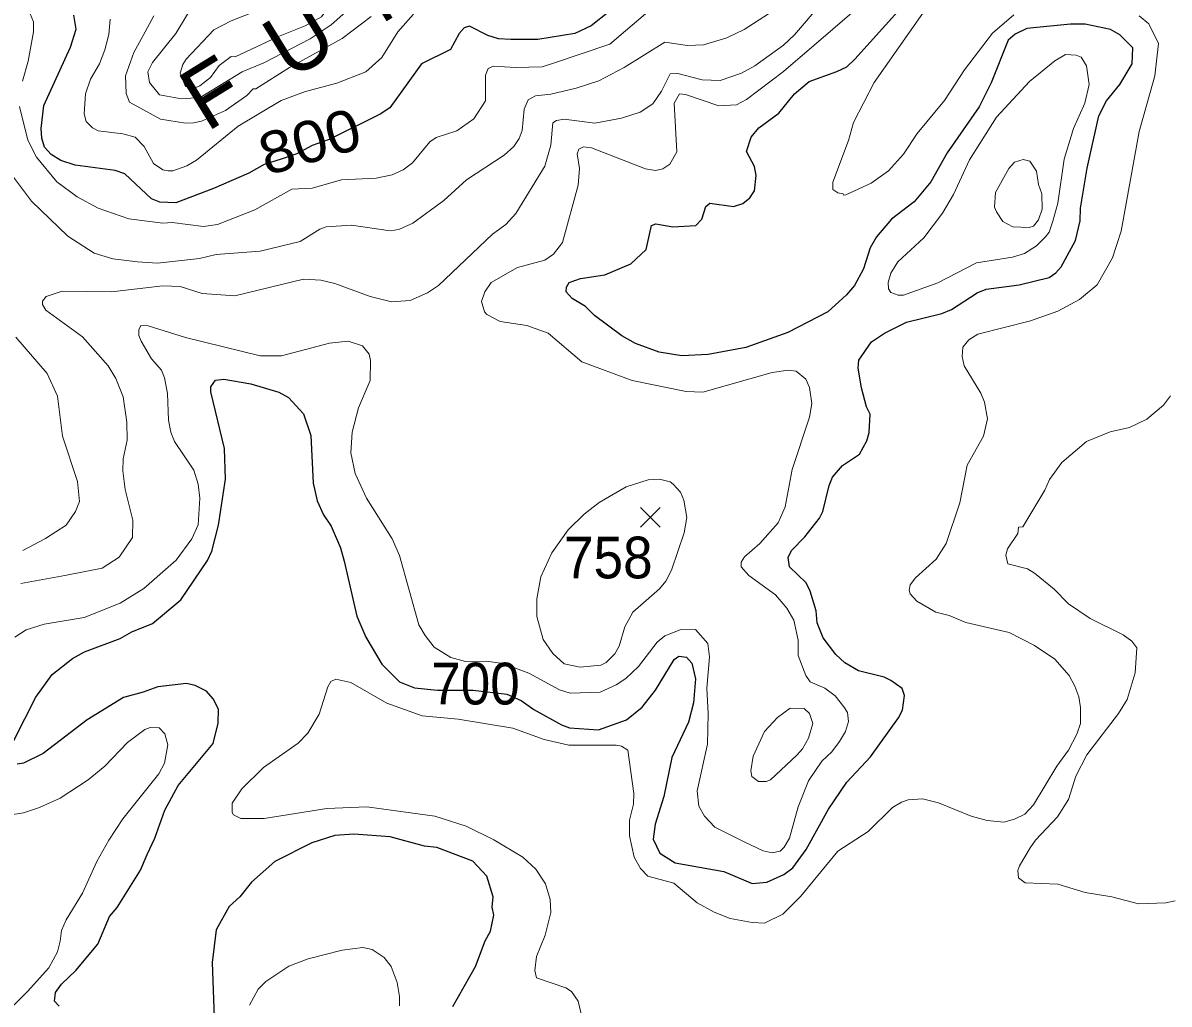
# Model space of a CAD drawing. Extents: x 294.2 to 320.3, y 7482.7 to 7510.7.
# Drawn here: x 308.568 to 310.764, y 7485.877 to 7487.757 of the extents above; entities that cross this region are included whole.
import ezdxf
from ezdxf.enums import TextEntityAlignment as Align

# ---------------------------------------------------------------- set-up
doc = ezdxf.new("R2010")
doc.units = 0
doc.header["$LTSCALE"] = 0.032
for name, color, linetype, lineweight in [('1', 7, 'Continuous', 25), ('2', 7, 'Continuous', 13), ('21', 7, 'Continuous', 25)]:
    doc.layers.add(name, color=color, linetype=linetype, lineweight=lineweight)
doc.layers.add('61', color=7, linetype='Continuous')

msp = doc.modelspace()

# ---------------------------------------------------------------- linework, layer by layer
at = {"layer": '1'}
for points in [[(309.6095, 7487.2508), (309.6145, 7487.26), (309.6361, 7487.2675), (309.6827, 7487.2745), (309.7327, 7487.2954), (309.7618, 7487.3232), (309.7724, 7487.369), (309.7801, 7487.3722), (309.8127, 7487.3666), (309.8571, 7487.3692), (309.8688, 7487.381), (309.8765, 7487.4058), (309.8837, 7487.4117), (309.9292, 7487.4053), (309.9469, 7487.4115), (309.9602, 7487.4222), (309.9697, 7487.4357), (309.9724, 7487.4652), (309.9696, 7487.4824), (309.9541, 7487.5109), (309.963, 7487.5383), (309.978, 7487.5566), (310.0162, 7487.5841), (310.0462, 7487.6213), (310.0742, 7487.6453), (310.1269, 7487.6641), (310.1463, 7487.6733), (310.1618, 7487.6878), (310.2794, 7487.819)], [(308.763, 7487.4681), (308.7447, 7487.4746), (308.6679, 7487.4848), (308.6401, 7487.4934), (308.6221, 7487.5052), (308.6088, 7487.5192), (308.6038, 7487.5364), (308.6027, 7487.5547), (308.608, 7487.5993), (308.6588, 7487.7106), (308.6699, 7487.7456), (308.6654, 7487.7725)], [(309.6902, 7487.7785), (309.6567, 7487.7517), (309.6251, 7487.7371), (309.5544, 7487.7253), (309.5028, 7487.7253), (309.4787, 7487.7269), (309.4582, 7487.7333), (309.4232, 7487.7511), (309.4133, 7487.7479), (309.4038, 7487.7371), (309.3867, 7487.7065), (309.3317, 7487.679), (309.271, 7487.5946), (309.2522, 7487.5822), (309.1545, 7487.5342), (309.1218, 7487.5223), (309.0927, 7487.5062), (309.0627, 7487.4965), (309.03, 7487.4857)], [(309.8491, 7486.5302), (309.8561, 7486.5002), (309.8523, 7486.4543), (309.8427, 7486.4172), (309.8108, 7486.3491), (309.7959, 7486.2743), (309.7793, 7486.2216), (309.7754, 7486.1931), (309.7882, 7486.1662), (309.8176, 7486.1474), (309.9109, 7486.1307), (309.9648, 7486.1076), (309.9931, 7486.1103), (310.0259, 7486.1254), (310.0426, 7486.1377), (310.0687, 7486.1733), (310.1109, 7486.2503), (310.1465, 7486.302), (310.1914, 7486.3504), (310.2452, 7486.4251), (310.253, 7486.4401), (310.2568, 7486.4681), (310.2524, 7486.4815), (310.2308, 7486.4971), (310.218, 7486.5036), (310.1687, 7486.5153), (310.1427, 7486.5307), (310.125, 7486.5468), (310.1012, 7486.5786), (310.0895, 7486.6076), (310.0878, 7486.6302), (310.0762, 7486.6684), (310.0684, 7486.684), (310.0368, 7486.7147), (310.034, 7486.733), (310.0401, 7486.7464), (310.0656, 7486.7722), (310.0939, 7486.8082), (310.1005, 7486.8211), (310.1122, 7486.8706), (310.1188, 7486.8867), (310.1383, 7486.9093), (310.1705, 7486.9309), (310.1845, 7486.9566), (310.189, 7486.9722), (310.1912, 7487.0072), (310.184, 7487.0212), (310.1745, 7487.0577), (310.1679, 7487.0959), (310.1695, 7487.1109), (310.1934, 7487.1464), (310.2183, 7487.163), (310.2605, 7487.184), (310.3282, 7487.2002), (310.3471, 7487.2083), (310.3963, 7487.2402), (310.4133, 7487.2468), (310.4766, 7487.2554), (310.5338, 7487.2691), (310.5466, 7487.2783), (310.5571, 7487.2901), (310.5843, 7487.3402), (310.5932, 7487.3778), (310.5943, 7487.402), (310.6065, 7487.4789), (310.6293, 7487.5794), (310.6437, 7487.6079), (310.6692, 7487.6396), (310.6931, 7487.6789), (310.6942, 7487.7095), (310.6692, 7487.7348), (310.6515, 7487.745), (310.6027, 7487.7547), (310.5749, 7487.7552), (310.4909, 7487.7466), (310.4687, 7487.7359), (310.4554, 7487.7246), (310.4226, 7487.6423), (310.3999, 7487.5965), (310.3386, 7487.5084), (310.3075, 7487.453), (310.2756, 7487.4146), (310.2318, 7487.3813), (310.203, 7487.3474), (310.1908, 7487.3264), (310.178, 7487.2861), (310.1608, 7487.2543), (310.1459, 7487.2361), (310.1098, 7487.2038), (310.0333, 7487.164), (309.9529, 7487.1354), (309.8808, 7487.1221), (309.8304, 7487.1194), (309.787, 7487.1264), (309.7415, 7487.1431)], [(309.03, 7487.4857), (309.0009, 7487.4696), (308.9327, 7487.44), (308.8608, 7487.4127), (308.8303, 7487.4138), (308.8143, 7487.4202), (308.763, 7487.4681)], [(309.7415, 7487.1431), (309.7154, 7487.1577), (309.6627, 7487.1965), (309.6455, 7487.2137), (309.6198, 7487.229), (309.6089, 7487.2417), (309.6095, 7487.2508)], [(308.5502, 7486.3819), (308.5924, 7486.4652), (308.6235, 7486.5082), (308.6628, 7486.5389), (308.6856, 7486.5518), (308.7538, 7486.5775), (308.7766, 7486.5904), (308.8157, 7486.6064), (308.8701, 7486.6516), (308.9217, 7486.7268), (308.93, 7486.7446), (308.9422, 7486.7946), (308.9561, 7486.8829), (308.9541, 7486.9416), (308.9275, 7487.0503), (308.9281, 7487.06), (308.9369, 7487.0724), (308.953, 7487.0745), (309.0046, 7487.0659), (309.0579, 7487.0498), (309.0767, 7487.0396), (309.1056, 7487.0078), (309.1195, 7486.9664), (309.1236, 7486.8749), (309.1314, 7486.8416), (309.1436, 7486.8147), (309.1586, 7486.7926), (309.1763, 7486.7512), (309.183, 7486.7254), (309.2074, 7486.6205), (309.2246, 7486.5802), (309.2557, 7486.528), (309.2895, 7486.4941), (309.3179, 7486.4829), (309.3618, 7486.4786), (309.4301, 7486.4786), (309.4951, 7486.471), (309.5222, 7486.4587), (309.5465, 7486.4414), (309.5995, 7486.4121), (309.6148, 7486.4063), (309.6703, 7486.4025), (309.724, 7486.4216)], [(309.724, 7486.4216), (309.754, 7486.4459), (309.7795, 7486.4785), (309.8153, 7486.5372), (309.8242, 7486.5436), (309.8389, 7486.5417), (309.8491, 7486.5302)], [(308.6375, 7485.8724), (308.6281, 7485.8821), (308.6303, 7485.8988), (308.6414, 7485.9149), (308.6691, 7485.9408), (308.7113, 7485.9913), (308.7339, 7486.0448), (308.7484, 7486.062), (308.7933, 7486.1335), (308.8061, 7486.1636), (308.8205, 7486.1948), (308.8394, 7486.2485), (308.8654, 7486.2959), (308.9325, 7486.3765), (308.9419, 7486.4152), (308.9425, 7486.4421), (308.9325, 7486.462), (308.9197, 7486.4765), (308.8975, 7486.4872), (308.8809, 7486.491), (308.826, 7486.4851), (308.7983, 7486.4743), (308.7605, 7486.4646), (308.6906, 7486.4216), (308.6068, 7486.357), (308.5691, 7486.3388), (308.5569, 7486.3366)], [(309.3915, 7485.8722), (309.4351, 7485.9486), (309.4535, 7485.9981), (309.4635, 7486.0164), (309.4701, 7486.047), (309.4668, 7486.0626), (309.4685, 7486.0825), (309.4568, 7486.1218), (309.4297, 7486.1509), (309.3607, 7486.1768), (309.3369, 7486.1795), (309.2714, 7486.1972), (309.202, 7486.2025), (309.1654, 7486.1999), (309.1215, 7486.1859), (309.0504, 7486.1503), (309.0054, 7486.1105), (308.9832, 7486.0825)], [(308.9832, 7486.0825), (308.9632, 7486.0636), (308.9382, 7486.019), (308.9305, 7485.9565), (308.9358, 7485.7983), (308.9497, 7485.7295), (308.9699, 7485.6695)]]:
    msp.add_lwpolyline(points, dxfattribs=at)
at = {"layer": '2'}
for points in [[(308.53, 7487.8576), (308.5722, 7487.7976), (308.5881, 7487.7593), (308.5881, 7487.7401), (308.5779, 7487.684), (308.5671, 7487.6456)], [(309.837, 7487.6201), (309.9009, 7487.5984), (309.9347, 7487.6003), (309.9538, 7487.6105), (310.0247, 7487.6641), (310.2143, 7487.8269), (310.2399, 7487.8691)], [(309.2317, 7487.8193), (309.1583, 7487.7535), (309.1182, 7487.7269), (309.0295, 7487.6811), (308.9878, 7487.6635), (308.9074, 7487.6144), (308.8716, 7487.6118), (308.8295, 7487.6195), (308.8103, 7487.6431), (308.8071, 7487.6635), (308.8161, 7487.6814), (308.8608, 7487.7369), (308.8978, 7487.7982)], [(308.5249, 7487.495), (308.5843, 7487.4158), (308.6539, 7487.3487), (308.7043, 7487.3161), (308.7401, 7487.3053), (308.7873, 7487.2995), (308.8257, 7487.297), (308.9061, 7487.3059), (308.938, 7487.3136), (309.0223, 7487.32), (309.0989, 7487.3385), (309.1366, 7487.3621), (309.1487, 7487.3666), (309.1972, 7487.3698), (309.2713, 7487.359), (309.2879, 7487.3615), (309.3147, 7487.3736), (309.3741, 7487.417), (309.4175, 7487.4566), (309.4897, 7487.5039), (309.5082, 7487.5205), (309.5184, 7487.5358), (309.5241, 7487.5512), (309.5279, 7487.592), (309.5356, 7487.6099), (309.5497, 7487.6175), (309.5791, 7487.6207), (309.6276, 7487.6322), (309.671, 7487.6463), (309.7195, 7487.6718), (309.7974, 7487.7203), (309.8408, 7487.714), (309.8717, 7487.7152), (309.9162, 7487.7286), (309.9494, 7487.7446), (310.0426, 7487.8052)], [(308.5613, 7487.5971), (308.5773, 7487.5326), (308.5939, 7487.5001), (308.6328, 7487.4528), (308.6717, 7487.4241), (308.712, 7487.4024), (308.7707, 7487.382), (308.8359, 7487.3736), (308.8537, 7487.3749), (308.9138, 7487.3672), (308.9406, 7487.3711), (309.0121, 7487.3992), (309.0829, 7487.4387), (309.1219, 7487.4407), (309.1781, 7487.4566), (309.2445, 7487.4598), (309.2751, 7487.4662), (309.2962, 7487.4758), (309.3141, 7487.4892), (309.3473, 7487.5294), (309.3594, 7487.5377), (309.399, 7487.5505), (309.4315, 7487.5735), (309.4539, 7487.608), (309.4539, 7487.6571), (309.459, 7487.6699), (309.4692, 7487.6744), (309.5114, 7487.6718), (309.5625, 7487.6731), (309.5842, 7487.6801), (309.6921, 7487.7169), (309.7776, 7487.7893)], [(310.0988, 7487.7963), (310.0458, 7487.7344), (310.0247, 7487.7146)], [(310.3133, 7487.8065), (310.199, 7487.6431), (310.1594, 7487.5665), (310.1498, 7487.532), (310.1192, 7487.4522), (310.1198, 7487.4381), (310.1294, 7487.4317), (310.1396, 7487.4298), (310.1402, 7487.4273), (310.1447, 7487.4279), (310.1932, 7487.4502), (310.2264, 7487.4739), (310.2552, 7487.5058), (310.2813, 7487.5454), (310.3337, 7487.6086), (310.372, 7487.6674), (310.4256, 7487.7376), (310.4665, 7487.7727)], [(309.3162, 7487.7739), (309.2862, 7487.7406), (309.2553, 7487.6909), (309.2247, 7487.6635), (309.1692, 7487.6418), (309.1091, 7487.6258), (309.0625, 7487.6086), (308.9801, 7487.5594), (308.9003, 7487.4943), (308.8818, 7487.4834), (308.855, 7487.4739), (308.8461, 7487.4739), (308.8359, 7487.4758), (308.8179, 7487.4879), (308.8001, 7487.5205), (308.7828, 7487.5384), (308.7593, 7487.5447), (308.712, 7487.5505), (308.7011, 7487.5563), (308.689, 7487.5684), (308.6851, 7487.5831), (308.6877, 7487.6214), (308.6973, 7487.6495), (308.7145, 7487.6789), (308.7247, 7487.7057), (308.7324, 7487.735), (308.7349, 7487.7644)], [(309.2347, 7487.7696), (309.1793, 7487.7276), (309.0782, 7487.6722), (309.014, 7487.6309), (309.0089, 7487.6309), (308.9967, 7487.6181), (308.9559, 7487.5894), (308.9099, 7487.569), (308.8946, 7487.5658), (308.8793, 7487.5652), (308.8314, 7487.5728), (308.772, 7487.6052), (308.7653, 7487.6224), (308.7643, 7487.6559), (308.7803, 7487.7006), (308.7982, 7487.7331), (308.8186, 7487.7708)], [(310.7066, 7487.7708), (310.7251, 7487.7554), (310.7436, 7487.7178), (310.7366, 7487.6559), (310.7277, 7487.6239), (310.7066, 7487.5492), (310.6721, 7487.3583), (310.6555, 7487.3073), (310.6261, 7487.2555), (310.5923, 7487.2274), (310.5508, 7487.2051), (310.4985, 7487.1866), (310.3976, 7487.161), (310.3803, 7487.1502)], [(310.0247, 7487.7146), (309.9698, 7487.675), (309.9443, 7487.6609), (309.9034, 7487.6469), (309.8689, 7487.6482), (309.8223, 7487.6603), (309.8076, 7487.6596)], [(309.8076, 7487.6596), (309.791, 7487.6265), (309.7744, 7487.6022), (309.7502, 7487.5863), (309.7144, 7487.5748), (309.6633, 7487.5652), (309.6046, 7487.5728), (309.5899, 7487.5703), (309.5829, 7487.5658), (309.579, 7487.5231), (309.5676, 7487.4826), (309.512, 7487.3921), (309.4928, 7487.3711), (309.4673, 7487.3526), (309.3639, 7487.2542), (309.3428, 7487.2402), (309.3096, 7487.2255), (309.2739, 7487.2229), (309.233, 7487.2331), (309.1653, 7487.2581), (309.1385, 7487.2645), (309.1053, 7487.2663), (308.9738, 7487.2344), (308.9112, 7487.2389), (308.8691, 7487.2523), (308.8359, 7487.2536), (308.7375, 7487.2421), (308.6431, 7487.2434), (308.6124, 7487.2332), (308.6054, 7487.2243), (308.6054, 7487.2179), (308.6118, 7487.207), (308.682, 7487.1559), (308.7311, 7487.1004), (308.7458, 7487.0761), (308.7599, 7487.0404), (308.7669, 7486.9918), (308.7675, 7486.9574), (308.7599, 7486.9216), (308.7592, 7486.8986), (308.7637, 7486.8629), (308.7784, 7486.8041), (308.7778, 7486.7709), (308.7522, 7486.7333), (308.7197, 7486.7122), (308.6482, 7486.6981), (308.5639, 7486.6828)], [(309.3383, 7486.5832), (309.3556, 7486.5609), (309.3875, 7486.541), (309.4156, 7486.5334), (309.4552, 7486.534), (309.4877, 7486.5295), (309.5369, 7486.5111), (309.5957, 7486.4791), (309.6161, 7486.4728), (309.6736, 7486.4746), (309.7042, 7486.4887), (309.7227, 7486.5009), (309.747, 7486.5238), (309.7827, 7486.5704), (309.7974, 7486.5826), (309.8268, 7486.5941), (309.8561, 7486.5947), (309.8798, 7486.5679), (309.8829, 7486.5424), (309.8778, 7486.4823), (309.8804, 7486.4338), (309.8791, 7486.3751), (309.8599, 7486.2857), (309.8625, 7486.2563), (309.8734, 7486.2372), (309.8932, 7486.2155), (309.9494, 7486.188), (309.9858, 7486.1707), (310.003, 7486.1669), (310.0183, 7486.1701), (310.026, 7486.1772), (310.0362, 7486.195), (310.0528, 7486.255), (310.0732, 7486.3048), (310.0987, 7486.3425), (310.1179, 7486.3604), (310.1326, 7486.3802), (310.1441, 7486.3993), (310.1498, 7486.4185), (310.1478, 7486.4355), (310.1409, 7486.4466), (310.1243, 7486.4677), (310.1039, 7486.4823), (310.0764, 7486.4945), (310.0681, 7486.5066), (310.0528, 7486.5449), (310.0528, 7486.5743), (310.0445, 7486.6126), (310.0311, 7486.6356), (310.0094, 7486.6611), (309.9583, 7486.6981), (309.9442, 7486.7147), (309.9442, 7486.7236), (309.95, 7486.7339), (309.9794, 7486.7594), (310.0145, 7486.799), (310.0279, 7486.8297), (310.0419, 7486.9012), (310.0745, 7487.002), (310.0796, 7487.0276), (310.0745, 7487.0583), (310.0675, 7487.0748), (310.049, 7487.0901), (310.0337, 7487.0921), (310.003, 7487.087), (309.8702, 7487.0499), (309.8383, 7487.0512), (309.7348, 7487.0717), (309.6384, 7487.108), (309.5739, 7487.1629), (309.5331, 7487.1776), (309.482, 7487.1853), (309.4564, 7487.1987), (309.452, 7487.2038), (309.4461, 7487.2233), (309.4526, 7487.2421), (309.4647, 7487.26), (309.5152, 7487.2887), (309.5676, 7487.3028), (309.5841, 7487.3143), (309.6014, 7487.3366), (309.6314, 7487.4464), (309.6339, 7487.4784), (309.6295, 7487.5065), (309.6326, 7487.5154), (309.6416, 7487.5199), (309.657, 7487.5179), (309.7604, 7487.4777), (309.7795, 7487.4745), (309.7936, 7487.4777), (309.807, 7487.4867), (309.8204, 7487.5103), (309.8152, 7487.6035), (309.8255, 7487.6213), (309.837, 7487.6201)], [(308.5524, 7486.58), (308.5741, 7486.5941), (308.6086, 7486.6049), (308.6852, 7486.6177), (308.7541, 7486.6451), (308.7994, 7486.6732), (308.8614, 7486.7275), (308.8914, 7486.7684), (308.9035, 7486.7952), (308.9067, 7486.8463), (308.9035, 7486.8731), (308.8952, 7486.8999), (308.8582, 7486.9548), (308.8511, 7486.9727), (308.8467, 7486.9957), (308.8448, 7487.0468), (308.8391, 7487.0774), (308.8333, 7487.0915), (308.8141, 7487.1132), (308.7944, 7487.1476), (308.7899, 7487.1585), (308.7899, 7487.1693), (308.7937, 7487.1776), (308.8078, 7487.177), (308.8793, 7487.1546), (309.0223, 7487.1195), (309.0632, 7487.1195), (309.1551, 7487.1438), (309.1909, 7487.1476), (309.2183, 7487.1387), (309.2311, 7487.1227), (309.2336, 7487.1106), (309.233, 7487.0723), (309.2106, 7487.0199), (309.1985, 7486.9727), (309.1959, 7486.9331)], [(308.5543, 7487.1553), (308.6143, 7487.0857), (308.6341, 7487.0417), (308.6437, 7486.965), (308.6724, 7486.8782), (308.6762, 7486.8399), (308.6686, 7486.8207), (308.6507, 7486.7945), (308.6111, 7486.769), (308.5677, 7486.746)], [(310.3803, 7487.1502), (310.3688, 7487.1361), (310.3676, 7487.1183), (310.3714, 7487.1004), (310.4033, 7487.048), (310.4103, 7487.0302), (310.4161, 7486.9982)], [(310.7666, 7487.0429), (310.7532, 7487.025), (310.7213, 7486.9976), (310.688, 7486.9817), (310.6507, 7486.9733), (310.6057, 7486.9548), (310.5585, 7486.9146), (310.5348, 7486.882), (310.5259, 7486.8616), (310.4837, 7486.7913), (310.4755, 7486.7907), (310.4742, 7486.7786), (310.4544, 7486.7492), (310.4512, 7486.7371), (310.455, 7486.7205), (310.4927, 7486.7109), (310.5061, 7486.7026), (310.5438, 7486.6719), (310.5712, 7486.6438), (310.6127, 7486.6158), (310.676, 7486.5845), (310.6925, 7486.5724), (310.7021, 7486.5596), (310.6989, 7486.5117), (310.6836, 7486.4606), (310.667, 7486.4338), (310.6064, 7486.3546), (310.5853, 7486.3138), (310.5712, 7486.2691), (310.5502, 7486.2359), (310.508, 7486.1912), (310.4978, 7486.1759), (310.4774, 7486.1414), (310.4742, 7486.1325), (310.4754, 7486.119), (310.4882, 7486.1094), (310.5508, 7486.1063), (310.6032, 7486.0903), (310.6543, 7486.082), (310.7053, 7486.0686), (310.7577, 7486.0705), (310.7756, 7486.0744)], [(310.4161, 7486.9982), (310.4084, 7486.965), (310.3771, 7486.9094), (310.3631, 7486.8373), (310.3369, 7486.7594), (310.3178, 7486.7294), (310.2781, 7486.6937), (310.268, 7486.6803), (310.266, 7486.6701), (310.2679, 7486.663), (310.2807, 7486.649), (310.3171, 7486.6279), (310.3427, 7486.6215), (310.3746, 7486.6081), (310.4576, 7486.589), (310.5061, 7486.564), (310.5451, 7486.5379), (310.5725, 7486.5066), (310.5834, 7486.4862), (310.591, 7486.4657), (310.5942, 7486.4453), (310.5942, 7486.4147), (310.5872, 7486.3942), (310.5712, 7486.3636), (310.5489, 7486.3329), (310.5042, 7486.2589), (310.4876, 7486.241), (310.4678, 7486.2314), (310.4474, 7486.2256), (310.4155, 7486.2289), (310.3848, 7486.2371), (310.3222, 7486.2627), (310.2916, 7486.2703), (310.2641, 7486.2684), (310.2513, 7486.2639), (310.2341, 7486.2537), (310.1869, 7486.2072), (310.1288, 7486.1701), (310.0579, 7486.0833), (310.0234, 7486.0488), (309.9889, 7486.0315), (309.9647, 7486.0328), (309.9226, 7486.0405), (309.8919, 7486.0526), (309.8593, 7486.0711), (309.8146, 7486.1082), (309.7648, 7486.1222), (309.7508, 7486.1363), (309.7386, 7486.158), (309.7297, 7486.1989), (309.7297, 7486.2295), (309.7374, 7486.2602), (309.738, 7486.2806), (309.7265, 7486.3635), (309.7144, 7486.3712), (309.7042, 7486.3732), (309.6135, 7486.3732), (309.5663, 7486.384), (309.5063, 7486.4057), (309.4016, 7486.4229), (309.3326, 7486.4293), (309.2649, 7486.4536), (309.196, 7486.4932), (309.1672, 7486.4996), (309.1576, 7486.4951), (309.1519, 7486.4849), (309.1353, 7486.4325), (309.1136, 7486.3961), (309.0951, 7486.377), (309.0287, 7486.3303), (308.9872, 7486.2895), (308.9686, 7486.262), (308.9686, 7486.2442), (308.9712, 7486.2397), (308.9852, 7486.2327), (309.03, 7486.2327), (309.15, 7486.2518), (309.2266, 7486.255), (309.3569, 7486.2371), (309.4169, 7486.218), (309.4699, 7486.1918), (309.5254, 7486.158), (309.5503, 7486.135), (309.5688, 7486.1069), (309.5777, 7486.0769), (309.579, 7486.052), (309.5682, 7486.0086), (309.5516, 7485.9677), (309.5484, 7485.9409), (309.5516, 7485.9269), (309.6078, 7485.9077), (309.6186, 7485.9007), (309.6314, 7485.8822), (309.6416, 7485.8388)], [(309.1959, 7486.9331), (309.2043, 7486.8935), (309.226, 7486.8463), (309.2751, 7486.7684), (309.2891, 7486.7365), (309.3262, 7486.6037), (309.3383, 7486.5832)], [(308.5025, 7485.8273), (308.5766, 7485.9007), (308.6175, 7485.946), (308.6341, 7485.9767), (308.6392, 7485.9971), (308.6417, 7486.0175), (308.6507, 7486.038), (308.682, 7486.089), (308.7094, 7486.1503), (308.7324, 7486.1912), (308.7592, 7486.2321), (308.8282, 7486.3182), (308.839, 7486.3386), (308.8454, 7486.3738), (308.8397, 7486.3949), (308.8288, 7486.4064), (308.8116, 7486.407), (308.8014, 7486.4031), (308.7682, 7486.3783), (308.7248, 7486.3329), (308.6929, 7486.3068), (308.6392, 7486.2716), (308.5996, 7486.2537), (308.569, 7486.2435), (308.5281, 7486.2371)], [(309.2891, 7485.8732), (309.2891, 7485.8911), (309.2847, 7485.9179), (309.2732, 7485.9486), (309.2598, 7485.9658), (309.2368, 7485.9811), (309.219, 7485.985), (309.1794, 7485.9799), (309.1142, 7485.9633), (309.0772, 7485.9492), (309.0331, 7485.9198), (309.0185, 7485.9051), (309.0018, 7485.8745)]]:
    msp.add_lwpolyline(points, dxfattribs=at)
for points in [[(309.15, 7487.8129), (309.1455, 7487.8154), (309.1225, 7487.8148), (309.0745, 7487.8041), (308.9666, 7487.7611), (308.9336, 7487.7443), (308.8805, 7487.6878), (308.8741, 7487.6776), (308.869, 7487.6609), (308.8792, 7487.6354), (308.8959, 7487.6322), (308.9067, 7487.6367), (308.9272, 7487.6527), (308.9438, 7487.6756), (308.9667, 7487.6929), (308.9744, 7487.6922), (309.0574, 7487.7312), (309.1088, 7487.7518), (309.1398, 7487.7688), (309.1596, 7487.7957)], [(310.545, 7487.6845), (310.4965, 7487.645), (310.4333, 7487.5767), (310.3816, 7487.4949), (310.351, 7487.4286), (310.3299, 7487.3928), (310.2941, 7487.3456), (310.2443, 7487.2996), (310.2309, 7487.2779), (310.2258, 7487.26), (310.2264, 7487.2479), (310.2309, 7487.2408), (310.2444, 7487.2357), (310.2546, 7487.2357), (310.321, 7487.2593), (310.395, 7487.2977), (310.464, 7487.3085), (310.487, 7487.3155), (310.51, 7487.3302), (310.5272, 7487.3475), (310.5342, 7487.3564), (310.5412, 7487.3775), (310.5508, 7487.412), (310.5629, 7487.4962), (310.5808, 7487.555), (310.6025, 7487.6035), (310.6108, 7487.6393), (310.6057, 7487.675), (310.5955, 7487.6916), (310.5859, 7487.6954), (310.5655, 7487.6967)], [(310.4645, 7487.3666), (310.4454, 7487.3768), (310.4333, 7487.3954), (310.4295, 7487.4043), (310.4314, 7487.4324), (310.457, 7487.4784), (310.4678, 7487.4905), (310.4844, 7487.4956), (310.4972, 7487.4924), (310.5099, 7487.4732), (310.5137, 7487.4477), (310.5201, 7487.4298), (310.5208, 7487.4005), (310.5137, 7487.38), (310.5042, 7487.3679), (310.4959, 7487.3654)], [(309.7233, 7486.8679), (309.6716, 7486.838), (309.6429, 7486.8156), (309.6122, 7486.7856), (309.581, 7486.7415), (309.5599, 7486.6956), (309.5522, 7486.6535), (309.5522, 7486.6196), (309.5644, 7486.5756), (309.5829, 7486.5487), (309.6046, 7486.5289), (309.6352, 7486.5226), (309.6748, 7486.5264), (309.685, 7486.5315), (309.7016, 7486.5481), (309.7099, 7486.5628), (309.7208, 7486.5998), (309.7361, 7486.6279), (309.7872, 7486.6726), (309.7993, 7486.6873), (309.8101, 7486.7084), (309.8344, 7486.7799), (309.8395, 7486.8092), (309.8339, 7486.8426), (309.8274, 7486.8578), (309.8134, 7486.8731), (309.8076, 7486.8775), (309.7872, 7486.8827), (309.7655, 7486.8814)], [(310.0508, 7486.3539), (310.0004, 7486.3068), (309.9915, 7486.3035), (309.9774, 7486.3035), (309.9641, 7486.3131), (309.9621, 7486.324), (309.9666, 7486.3521), (309.9889, 7486.3993), (310.0138, 7486.4261), (310.0375, 7486.444), (310.0643, 7486.4434), (310.0751, 7486.4338), (310.0809, 7486.4147), (310.0732, 7486.3866), (310.0617, 7486.3661)]]:
    msp.add_lwpolyline(points, close=True, dxfattribs=at)
at = {"layer": '21'}
for p, q in [((309.751, 7486.8285), (309.7885, 7486.791)), ((309.7885, 7486.8285), (309.751, 7486.791))]:
    msp.add_line(p, q, dxfattribs=at)

# ---------------------------------------------------------------- texts
at = {"layer": '61'}
msp.add_text('F  U  N  D  Ã  O', height=0.12, rotation=31.751, dxfattribs=at).set_placement((309.3975, 7487.8427), align=Align.CENTER)
at = {"layer": '61', "width": 1.1}
msp.add_text('800', height=0.08, rotation=16.364, dxfattribs=at).set_placement((309.1286, 7487.4917), align=Align.CENTER)
at = {"layer": '61', "width": 0.95}
for s, p in [('758', (309.6894, 7486.6927)), ('700', (309.4349, 7486.451))]:
    msp.add_text(s, height=0.08, dxfattribs=at).set_placement(p, align=Align.CENTER)

doc.saveas('drawing.dxf')
